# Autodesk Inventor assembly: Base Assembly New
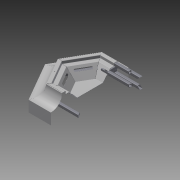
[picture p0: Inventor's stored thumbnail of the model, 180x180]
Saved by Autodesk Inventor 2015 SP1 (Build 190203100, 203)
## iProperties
Created: 2014-12
Part Number: Base Assembly New
Document SubType Name: Assembly
Designer: rsheridan
Author: rsheridan
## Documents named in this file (5)
- \\psf\Home\Documents\Inventor\Sau Paulo Chimnea\Base Assembly New.iam
- \\psf\Home\Documents\Inventor\Sau Paulo Chimnea\Outer Base and Frame\Frame\Frame0001.iam
- \\psf\Home\Documents\Inventor\Sau Paulo Chimnea\Outer Base.iam
- \\psf\Home\Documents\Inventor\Sau Paulo Chimnea\Fire Tray.ipt
- \\psf\Home\Documents\Inventor\Sau Paulo Chimnea\Base Assembly\Design Accelerator\Bolted Connection1.iam
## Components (4 placed, 4 different names)
1. Frame0001:1 [sub-assembly] — Mate:3
2. Outer Base:1 [sub-assembly] — Mate:1, Mate:2, Mate:3, Mate:5, Mate:6, Flush:1
3. Fire Tray:1 — Mate:5, Mate:6, Flush:1, Mate:7, Mate:8
4. Bolted Connection:1 [sub-assembly] — Mate:7, Mate:8
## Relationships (8: Mate 7, Flush 1)
- Mate:1: Outer Base:1
- Mate:2: Outer Base:1
- Mate:3: Frame0001:1 ↔ Outer Base:1
- Mate:5: Outer Base:1 ↔ Fire Tray:1
- Mate:6: Outer Base:1 ↔ Fire Tray:1
- Flush:1: Outer Base:1 ↔ Fire Tray:1
- Mate:7: Fire Tray:1 ↔ Bolted Connection:1
- Mate:8: Fire Tray:1 ↔ Bolted Connection:1
